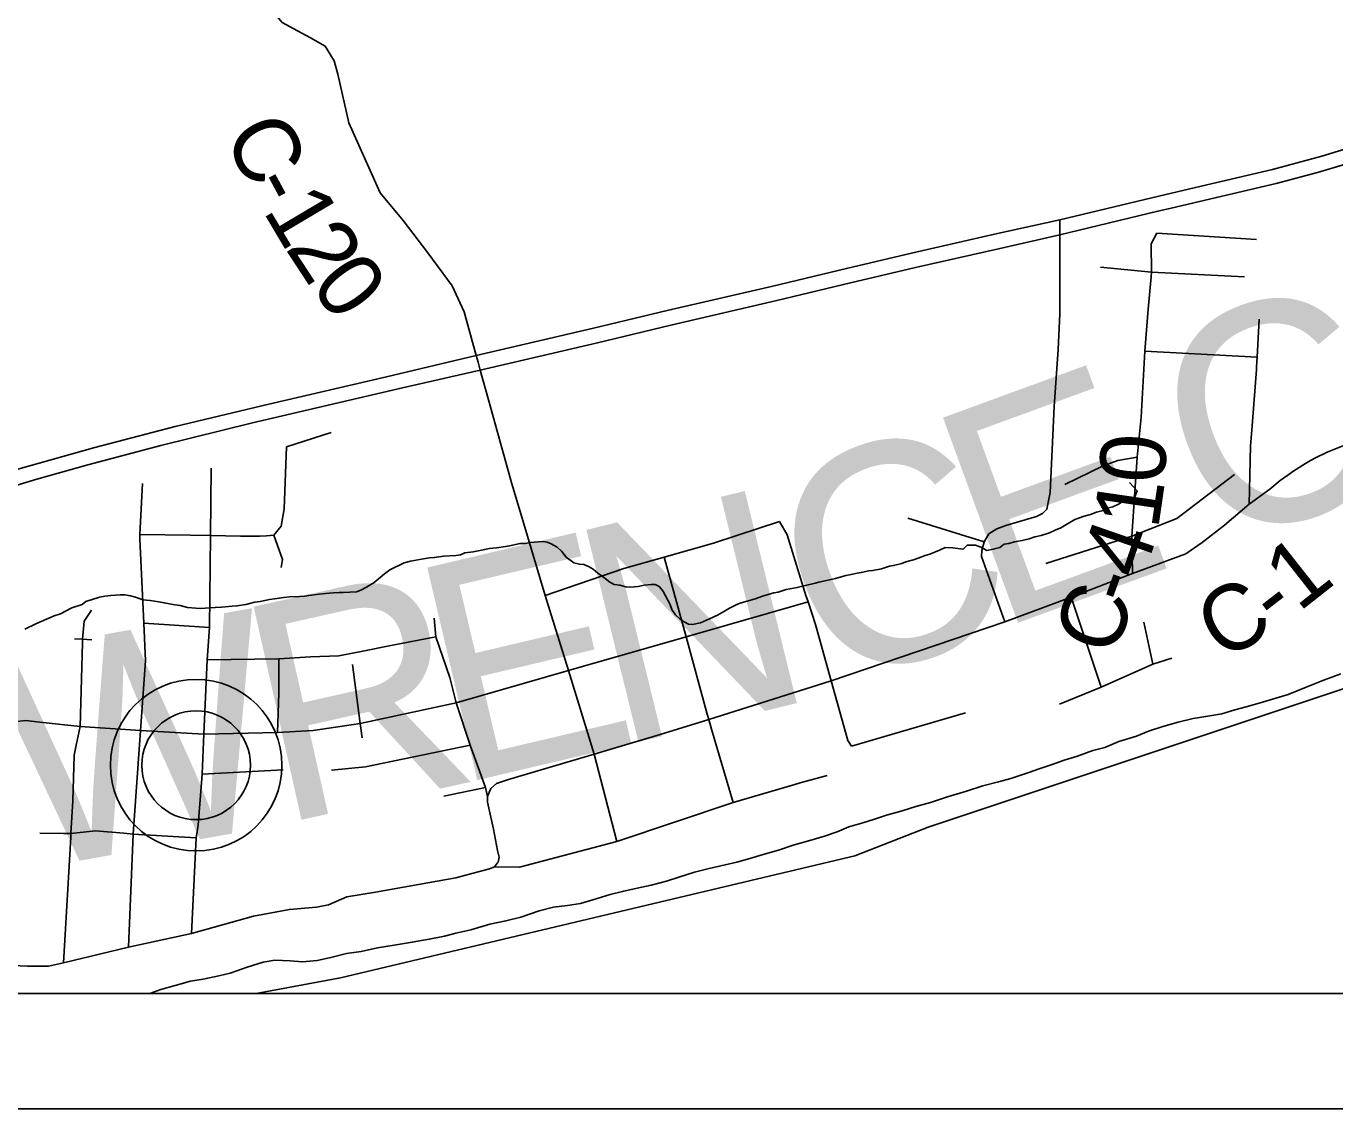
# Model space of a CAD drawing. Extents: x 0 to 45.4, y -2.2 to 22.
# Drawn here: x 6.842 to 7.977, y 14 to 14.939 of the extents above; entities that cross this region are included whole.
import ezdxf

# ---------------------------------------------------------------- set-up
doc = ezdxf.new("R2010")
doc.units = 0
for name, color, linetype in [('GM_X_Corporation', 7, 'Continuous'), ('GM_X_County_Road', 7, 'Continuous'), ('GM_X_County_Road_Text', 7, 'Continuous'), ('GM_X_County_Text', 7, 'Continuous'), ('GM_X_Major_River', 7, 'Continuous'), ('GM_X_Minor_River', 7, 'Continuous'), ('GM_X_Township_Road', 7, 'Continuous'), ('GM_X_Unincorporated', 7, 'Continuous'), ('GM_X_Unincorporated_Location', 7, 'Continuous'), ('GM_X_US_Route', 7, 'Continuous'), ('SH_Data', 7, 'Continuous')]:
    doc.layers.add(name, color=color, linetype=linetype)

msp = doc.modelspace()

# ---------------------------------------------------------------- linework, layer by layer
at = {"layer": 'GM_X_Corporation'}
for points in [[(5.6021, 14.1), (7.0413, 14.1), (7.1146, 14.1136), (7.5608, 14.2194), (7.6244, 14.2444), (8.0832, 14.3972), (8.4711, 14.5406), (8.5907, 14.5823), (8.8228, 14.6772), (8.9, 14.7192), (8.9, 20.9), (2.1, 20.9)], [(5.6021, 14.1), (7.0413, 14.1), (7.1146, 14.1136), (7.5608, 14.2194), (7.6244, 14.2444), (8.0832, 14.3972), (8.4711, 14.5406), (8.5907, 14.5823), (8.8228, 14.6772), (8.9, 14.7192), (8.9, 20.9), (6.2942, 20.9), (6.2882, 20.8226), (6.2789, 20.7002), (6.2588, 20.2929), (6.2538, 20.2076), (6.2346, 20.0088), (6.2236, 19.8542), (6.181, 19.2539), (6.1763, 19.1885), (6.1061, 18.1607), (5.642, 18.1908)]]:
    msp.add_lwpolyline(points, dxfattribs=at)
at = {"layer": 'GM_X_County_Road'}
for points in [[(7.2323, 14.6533), (7.2219, 14.6911), (7.2115, 14.7136), (7.1903, 14.7423), (7.169, 14.7705), (7.1488, 14.7944), (7.1219, 14.8551), (7.1121, 14.8973), (7.109, 14.909), (7.1011, 14.9216), (7.0886, 14.9288), (7.0772, 14.9349), (7.064, 14.9421), (7.0068, 15.0105), (6.9882, 15.0375), (6.9785, 15.0483), (6.9672, 15.0617), (6.9622, 15.0719), (6.9553, 15.0924), (6.9485, 15.1296), (6.9396, 15.1541)], [(7.6909, 14.4223), (7.6705, 14.479), (7.6708, 14.4841), (7.6729, 14.4917), (7.6771, 14.4986), (7.684, 14.5031), (7.6916, 14.5059), (7.7182, 14.5137), (7.7234, 14.5163), (7.7274, 14.52), (7.7303, 14.5344), (7.7337, 14.6091), (7.7372, 14.6586), (7.7386, 14.6895), (7.7386, 14.758), (7.7386, 14.771)], [(7.243, 14.6149), (7.2358, 14.6407), (7.2339, 14.6475), (7.2323, 14.6533)], [(7.2696, 14.521), (7.2633, 14.5419), (7.243, 14.6149)], [(7.2507, 14.2132), (7.2513, 14.2139), (7.2521, 14.2182), (7.2508, 14.2241), (7.2474, 14.2426), (7.2422, 14.2659), (7.2422, 14.2708), (7.2449, 14.2778), (7.2498, 14.2822), (7.2602, 14.2857), (7.3346, 14.3077), (7.3918, 14.3246), (7.434, 14.3375), (7.5402, 14.3711), (7.6909, 14.4223), (7.7483, 14.4437), (7.8016, 14.4643), (7.8478, 14.4813), (7.8621, 14.491), (7.8813, 14.5063), (7.9029, 14.5244), (7.9207, 14.5375), (7.9298, 14.5448), (7.9365, 14.5496), (7.9415, 14.5533), (7.9541, 14.561), (7.9599, 14.5644), (7.9704, 14.5694), (7.9762, 14.5719), (7.9937, 14.5788)], [(7.3346, 14.3077), (7.3123, 14.3801), (7.2922, 14.4452), (7.2696, 14.521)], [(6.8112, 14.1252), (6.843, 14.1237), (6.8612, 14.1237), (6.8743, 14.1267), (6.9307, 14.1402), (6.9853, 14.152), (7.0392, 14.1672), (7.0702, 14.1729), (7.0938, 14.1749), (7.104, 14.1769), (7.1201, 14.1837), (7.1448, 14.1878), (7.2145, 14.2004), (7.234, 14.2054), (7.2437, 14.208), (7.2481, 14.21), (7.2507, 14.2132)]]:
    msp.add_lwpolyline(points, dxfattribs=at)
at = {"layer": 'GM_X_Major_River'}
msp.add_lwpolyline([(7.9823, 14.3771), (7.9668, 14.3714), (7.9524, 14.3657), (7.9366, 14.3593), (7.926, 14.3562), (7.9116, 14.3517), (7.9003, 14.3486), (7.8904, 14.346), (7.8791, 14.3426), (7.8651, 14.3403), (7.8541, 14.3384), (7.8413, 14.3354), (7.828, 14.3316), (7.8155, 14.3274), (7.805, 14.3233), (7.7898, 14.3187), (7.7777, 14.3134), (7.7671, 14.3108), (7.7539, 14.3058), (7.7422, 14.3024), (7.732, 14.2986), (7.7214, 14.2952), (7.7108, 14.2914), (7.696, 14.2865), (7.6854, 14.2835), (7.6718, 14.2801), (7.6575, 14.2755), (7.6412, 14.2706), (7.6264, 14.2657), (7.6136, 14.2623), (7.6019, 14.2585), (7.5883, 14.2547), (7.5777, 14.2513), (7.5678, 14.2479), (7.5554, 14.2445), (7.5455, 14.2403), (7.5345, 14.2365), (7.5217, 14.2327), (7.5073, 14.2286), (7.4945, 14.2244), (7.4812, 14.2206), (7.4695, 14.2172), (7.4585, 14.2138), (7.4483, 14.2115), (7.4343, 14.2085), (7.4215, 14.2051), (7.4079, 14.2009), (7.3973, 14.1975), (7.384, 14.1941), (7.3719, 14.1914), (7.3602, 14.1888), (7.3485, 14.1858), (7.3334, 14.1812), (7.3228, 14.1782), (7.3114, 14.1763), (7.2993, 14.1748), (7.2868, 14.1717), (7.271, 14.1661), (7.2581, 14.163), (7.2441, 14.16), (7.2275, 14.1551), (7.2146, 14.1524), (7.2048, 14.1498), (7.1915, 14.1471), (7.1768, 14.1445), (7.1628, 14.1422), (7.1465, 14.1396), (7.1325, 14.1365), (7.1197, 14.1346), (7.1061, 14.1312), (7.0944, 14.1286), (7.0815, 14.1274), (7.0709, 14.1282), (7.0577, 14.129), (7.0475, 14.1271), (7.0335, 14.1229), (7.0187, 14.1176), (7.0089, 14.1153), (6.9953, 14.1123), (6.9843, 14.1108), (6.9711, 14.107), (6.9586, 14.1036), (6.949, 14.1)], dxfattribs=at)
at = {"layer": 'GM_X_Minor_River'}
for points in [[(7.3942, 14.4492), (7.3964, 14.4449), (7.4001, 14.438), (7.4019, 14.4331), (7.4052, 14.4285), (7.4093, 14.4246), (7.4127, 14.4223), (7.4165, 14.4203), (7.4199, 14.4199), (7.4267, 14.4216), (7.4347, 14.4249), (7.4416, 14.4282), (7.4477, 14.4315), (7.4519, 14.4341), (7.4588, 14.4378), (7.4622, 14.4389), (7.4672, 14.4403), (7.4714, 14.4414), (7.4752, 14.4425), (7.4805, 14.4446), (7.4904, 14.4475), (7.4942, 14.4482), (7.5011, 14.4504), (7.5106, 14.4521), (7.5178, 14.4539), (7.5262, 14.456), (7.5296, 14.4567), (7.5361, 14.4581), (7.544, 14.4599), (7.5528, 14.4624), (7.5562, 14.4631), (7.5627, 14.4645), (7.5661, 14.4652), (7.5729, 14.4666), (7.5764, 14.4669), (7.584, 14.4683), (7.5908, 14.4705), (7.5942, 14.4712), (7.6015, 14.473), (7.6049, 14.4744), (7.6117, 14.4762), (7.6156, 14.4776), (7.6217, 14.4798), (7.6258, 14.4809), (7.6342, 14.4845), (7.6392, 14.4867), (7.6456, 14.4866), (7.6502, 14.4858), (7.6547, 14.4853), (7.6582, 14.4887), (7.6654, 14.4889), (7.6699, 14.487), (7.6751, 14.4842), (7.6808, 14.4853), (7.6865, 14.4867), (7.6904, 14.4897), (7.6942, 14.4904), (7.6991, 14.4918), (7.706, 14.4928), (7.7121, 14.4942), (7.717, 14.496), (7.7223, 14.4971), (7.7296, 14.4996), (7.7345, 14.5018), (7.7395, 14.504), (7.7437, 14.5066), (7.7517, 14.511), (7.7598, 14.5139), (7.7651, 14.5153), (7.7704, 14.5175), (7.7761, 14.5189), (7.7799, 14.5208), (7.7845, 14.5222), (7.7895, 14.5244), (7.7941, 14.5274), (7.8002, 14.5292), (7.8036, 14.5306), (7.8056, 14.5359), (7.7989, 14.5432)], [(6.8406, 14.4161), (6.8502, 14.4205), (6.8548, 14.4227), (6.8662, 14.4274), (6.8716, 14.4292), (6.8815, 14.4344), (6.8903, 14.4373), (6.8937, 14.4399), (6.9055, 14.4438), (6.9101, 14.4445), (6.9154, 14.4452), (6.9192, 14.4455), (6.9234, 14.4458), (6.9275, 14.4457), (6.9324, 14.4449), (6.9366, 14.4437), (6.943, 14.4413), (6.9494, 14.4408), (6.957, 14.4396), (6.9615, 14.4387), (6.9709, 14.437), (6.9755, 14.4366), (6.9819, 14.4349), (6.9891, 14.4341), (6.9928, 14.434), (7.0057, 14.4349), (7.0114, 14.4352), (7.0205, 14.4358), (7.0247, 14.4361), (7.0323, 14.4375), (7.0403, 14.4393), (7.0448, 14.4399), (7.0528, 14.4417), (7.0574, 14.4424), (7.0654, 14.4434), (7.0703, 14.4441), (7.079, 14.4443), (7.0836, 14.4446), (7.087, 14.4453), (7.0961, 14.4463), (7.1014, 14.447), (7.1086, 14.4476), (7.1135, 14.4479), (7.1169, 14.4478), (7.1283, 14.4484), (7.1321, 14.4498), (7.1371, 14.4524), (7.1436, 14.4565), (7.149, 14.4609), (7.1528, 14.4639), (7.1574, 14.4673), (7.1697, 14.4735), (7.1754, 14.4749), (7.1849, 14.4767), (7.1917, 14.4777), (7.1959, 14.478), (7.2039, 14.4794), (7.2145, 14.48), (7.2187, 14.4803), (7.2225, 14.4821), (7.2297, 14.4831), (7.2396, 14.4852), (7.2434, 14.4859), (7.2498, 14.4866), (7.2578, 14.4876), (7.2612, 14.4883), (7.2703, 14.4904), (7.2749, 14.4903), (7.2791, 14.491), (7.2825, 14.4913), (7.2859, 14.4916), (7.2904, 14.4919), (7.2938, 14.4915), (7.2972, 14.4899), (7.3025, 14.4872), (7.3062, 14.4837), (7.3103, 14.4783), (7.317, 14.4736), (7.3219, 14.4724), (7.3257, 14.472), (7.3298, 14.4704), (7.3336, 14.468), (7.3377, 14.4646), (7.344, 14.4599), (7.3482, 14.4568), (7.3519, 14.4548), (7.3568, 14.454), (7.3621, 14.4527), (7.3659, 14.4523), (7.3727, 14.4529), (7.378, 14.454), (7.3841, 14.4546), (7.3875, 14.4546), (7.3909, 14.453), (7.3942, 14.4492)]]:
    msp.add_lwpolyline(points, dxfattribs=at)
at = {"layer": 'GM_X_Township_Road'}
for p, q in [((7.8228, 14.7594), (7.9091, 14.7539)), ((7.8122, 14.6571), (7.9097, 14.6519)), ((7.0677, 14.5742), (7.1063, 14.5864)), ((7.4583, 14.4972), (7.4953, 14.5093)), ((7.6729, 14.4917), (7.6067, 14.5123)), ((6.9405, 14.498), (6.9842, 14.4974)), ((7.7265, 14.473), (7.8011, 14.4965)), ((7.7745, 14.3658), (7.7483, 14.4437)), ((6.9438, 14.4212), (7.001, 14.4174)), ((7.8192, 14.3856), (7.8114, 14.422)), ((7.1582, 14.4017), (7.1973, 14.4092)), ((7.5578, 14.3146), (7.6566, 14.3434)), ((7.3542, 14.2317), (7.3346, 14.3077)), ((6.9944, 14.2903), (7.0648, 14.294)), ((7.2041, 14.2712), (7.2404, 14.2788)), ((7.4809, 14.2732), (7.5086, 14.2813)), ((6.8538, 14.239), (6.8743, 14.2387))]:
    msp.add_line(p, q, dxfattribs=at)
for points in [[(7.8177, 14.7216), (7.8181, 14.7256), (7.8177, 14.7503), (7.8228, 14.7594)], [(7.7739, 14.73), (7.8181, 14.7256), (7.8989, 14.7216)], [(7.8016, 14.4643), (7.8011, 14.4965), (7.8057, 14.5651), (7.809, 14.5999), (7.8122, 14.6571), (7.8151, 14.6934), (7.8177, 14.7216)], [(7.9092, 14.6427), (7.9095, 14.6482), (7.9097, 14.6519), (7.9115, 14.6847)], [(7.9053, 14.5922), (7.9091, 14.6411), (7.9092, 14.6427)], [(7.9029, 14.5244), (7.9039, 14.575), (7.9051, 14.5888), (7.9053, 14.5922)], [(7.0631, 14.4695), (7.0643, 14.4763), (7.0567, 14.4976), (7.0631, 14.5052), (7.0658, 14.5204), (7.0677, 14.5742)], [(6.9853, 14.152), (6.9893, 14.235), (6.991, 14.2461), (6.9944, 14.2903), (6.9959, 14.3249), (6.9988, 14.3893), (7.001, 14.4174), (7.0017, 14.4971), (7.0022, 14.5557)], [(7.7428, 14.5413), (7.7763, 14.5575), (7.7888, 14.5622), (7.8057, 14.5651)], [(7.8011, 14.4965), (7.84, 14.512), (7.89, 14.5502)], [(6.9404, 14.4947), (6.9405, 14.498), (6.9427, 14.5424)], [(7.5183, 14.4452), (7.5021, 14.4978), (7.4953, 14.5093)], [(6.9307, 14.1402), (6.9347, 14.2383), (6.9411, 14.328), (6.9453, 14.3884), (6.9438, 14.4212), (6.9404, 14.4939), (6.9404, 14.4947)], [(6.9842, 14.4974), (7.0017, 14.4971), (7.0279, 14.4967)], [(7.0279, 14.4967), (7.0446, 14.4965), (7.0503, 14.4968), (7.0567, 14.4976)], [(7.2922, 14.4452), (7.3602, 14.4687), (7.3952, 14.4785), (7.438, 14.4905), (7.4583, 14.4972)], [(7.4327, 14.3424), (7.4144, 14.4094), (7.3952, 14.4785)], [(7.5578, 14.3146), (7.5546, 14.3194), (7.5402, 14.3711), (7.5265, 14.4199), (7.5201, 14.4396), (7.5183, 14.4452)], [(6.8906, 14.4042), (6.8907, 14.4072), (6.8923, 14.4229), (6.8984, 14.4324)], [(7.2148, 14.3522), (7.3123, 14.3801), (7.4144, 14.4094), (7.5201, 14.4396)], [(7.2093, 14.3741), (7.1973, 14.4092), (7.1959, 14.4255)], [(6.8837, 14.4077), (6.8907, 14.4072), (6.8988, 14.4067)], [(6.8852, 14.3154), (6.8886, 14.3316), (6.8906, 14.4042)], [(6.9988, 14.3893), (7.0609, 14.3902), (7.0885, 14.392), (7.113, 14.3929), (7.1338, 14.397), (7.1582, 14.4017)], [(7.06, 14.3265), (7.0609, 14.3603), (7.0609, 14.3902)], [(7.1332, 14.3218), (7.1316, 14.3341), (7.1248, 14.3854)], [(7.7383, 14.351), (7.7745, 14.3658), (7.8192, 14.3856), (7.8357, 14.3908)], [(7.2422, 14.2708), (7.2404, 14.2788), (7.2271, 14.3153), (7.2148, 14.3522), (7.2093, 14.3741)], [(6.8886, 14.3316), (6.9411, 14.328), (6.9959, 14.3249), (7.06, 14.3265), (7.0908, 14.328), (7.1316, 14.3341), (7.2148, 14.3522)], [(6.5988, 14.3488), (6.7041, 14.3425), (6.7253, 14.3411), (6.7481, 14.3381), (6.7605, 14.3355), (6.781, 14.3339), (6.81, 14.3342), (6.8266, 14.3351), (6.8413, 14.3368), (6.8537, 14.3354), (6.8886, 14.3316)], [(7.4551, 14.2656), (7.4363, 14.3293), (7.434, 14.3375), (7.4327, 14.3424)], [(6.8806, 14.2357), (6.8807, 14.2387), (6.8824, 14.267), (6.8834, 14.3068), (6.8852, 14.3154)], [(7.1067, 14.2936), (7.1362, 14.2966), (7.2271, 14.3153)], [(7.5086, 14.2813), (7.5132, 14.2827), (7.5367, 14.2891)], [(7.2481, 14.21), (7.2698, 14.2097), (7.3542, 14.2317), (7.4551, 14.2656), (7.4809, 14.2732)], [(6.8743, 14.2387), (6.8764, 14.2387), (6.8807, 14.2387), (6.902, 14.241), (6.9265, 14.239)], [(6.9265, 14.239), (6.9347, 14.2383), (6.9893, 14.235)], [(6.8743, 14.1267), (6.8787, 14.2006), (6.8806, 14.2357)]]:
    msp.add_lwpolyline(points, dxfattribs=at)
at = {"layer": 'GM_X_Unincorporated'}
for radius in [0.0744, 0.0472]:
    msp.add_circle((6.9893, 14.298), radius, dxfattribs=at)
at = {"layer": 'GM_X_Unincorporated_Location'}
msp.add_line((6.9893, 14.298), (6.9893, 14.298), dxfattribs=at)
at = {"layer": 'GM_X_US_Route'}
for points in [[(6.8345, 14.5546), (6.9013, 14.5734), (6.971, 14.5918), (7.0523, 14.611), (7.1543, 14.6349), (7.2323, 14.6533), (7.3339, 14.677), (7.3978, 14.6923), (7.4895, 14.7135), (7.5534, 14.7288), (7.61, 14.7421), (7.6818, 14.7584), (7.7386, 14.771), (7.8123, 14.7887), (7.8244, 14.7916), (7.8562, 14.7991), (7.923, 14.8146), (7.9658, 14.8261), (8.0084, 14.8392)], [(6.7906, 14.5278), (6.8511, 14.5462), (6.8952, 14.5586), (6.9587, 14.5754), (7.0382, 14.5949), (7.1038, 14.6102), (7.1683, 14.6252), (7.2358, 14.6407), (7.3374, 14.6644), (7.4012, 14.6797), (7.493, 14.7009), (7.5569, 14.7162), (7.6134, 14.7295), (7.6853, 14.7458), (7.7386, 14.758), (7.8237, 14.7784), (7.8352, 14.7812), (7.9261, 14.8024), (7.9622, 14.8121), (7.9952, 14.8218)]]:
    msp.add_lwpolyline(points, dxfattribs=at)
at = {"layer": 'SH_Data'}
for p, q in [((2.1, 14.1), (8.9, 14.1)), ((2, 14), (9, 14))]:
    msp.add_line(p, q, dxfattribs=at)

# ---------------------------------------------------------------- texts
at = {"layer": 'GM_X_County_Road_Text'}
for s, rotation, p in [('C', 297.4718, (7.0123, 14.8439)), ('-', 298.4085, (7.0343, 14.8016)), ('1', 300.6802, (7.0467, 14.7789)), ('2', 303.2559, (7.066, 14.7465)), ('0', 306.8623, (7.0874, 14.714)), ('0', 86.7269, (7.8293, 14.5416)), ('1', 81.6999, (7.8237, 14.5016)), ('4', 70.8715, (7.8095, 14.4571)), ('1', 38.261, (7.9458, 14.4302)), ('-', 70.1263, (7.8013, 14.4344)), ('C', 69.9539, (7.7852, 14.3904)), ('C', 29.5236, (7.8789, 14.3877)), ('-', 37.6716, (7.9268, 14.4155))]:
    msp.add_text(s, height=0.0568, rotation=rotation, dxfattribs=at).set_placement(p)
at = {"layer": 'GM_X_County_Text'}
for s, rotation, p in [('C', 20.0779, (7.8698, 14.4828)), ('E', 20.1003, (7.6828, 14.4144)), ('C', 20.5769, (7.5389, 14.3604)), ('N', 13.7877, (7.3528, 14.3132)), ('E', 13.245, (7.213, 14.2803)), ('R', 12.6404, (7.0604, 14.2461)), ('W', 10.0758, (6.8364, 14.206))]:
    msp.add_text(s, height=0.1894, rotation=rotation, dxfattribs=at).set_placement(p)

doc.saveas('drawing.dxf')
